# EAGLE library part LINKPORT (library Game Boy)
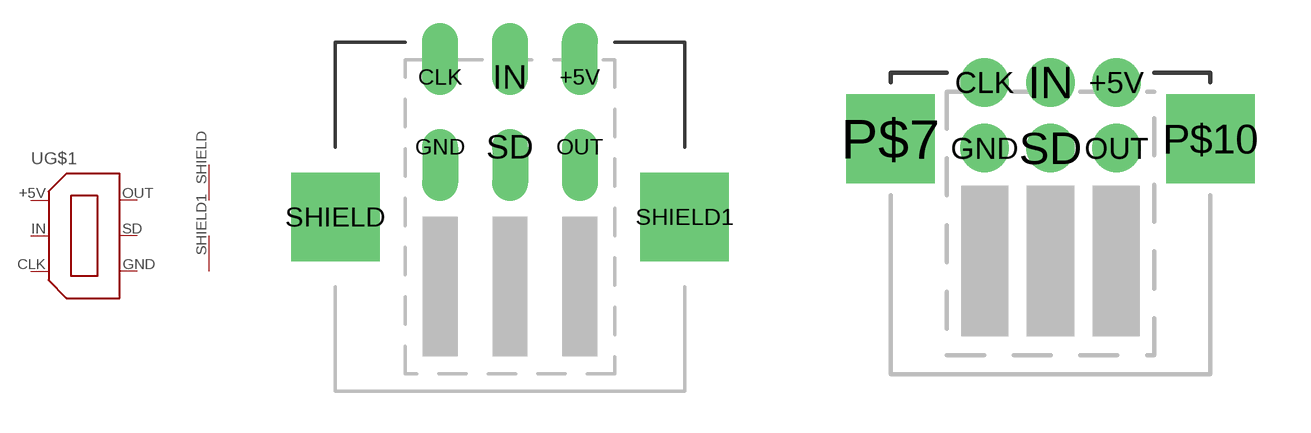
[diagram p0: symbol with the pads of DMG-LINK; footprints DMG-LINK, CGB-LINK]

Designator prefix -; gates G$1=LINK G$2=PWRGND G$3=PWRGND

## LINKPORTDMG-LINK  [DMG-LINK]
+5V  G$1:+5V
CLK  G$1:CLK
GND  G$1:GND
IN  G$1:IN
OUT  G$1:OUT
SD  G$1:SD
SHIELD  G$2:GND  pwr
SHIELD1  G$3:GND  pwr

## LINKPORTCGB-LINK  [CGB-LINK]
+5V  G$1:+5V
CLK  G$1:CLK
GND  G$1:GND
IN  G$1:IN
OUT  G$1:OUT
P$7  G$2:GND  pwr
P$10  G$3:GND  pwr
SD  G$1:SD

## Footprint DMG-LINK (pad centres in mm)
drill 0.8 offset: +5V 2.54,5.08; CLK -2.54,5.08; GND -2.54,2.54; IN 0,5.08; OUT 2.54,2.54; SD 0,2.54
drill 2.2 square: SHIELD -6.35,0; SHIELD1 6.35,0

## Footprint CGB-LINK (pad centres in mm)
drill 0.8 round: +5V 1.778,1.778; CLK -1.778,1.778; GND -1.778,0; IN 0,1.778; OUT 1.778,0; SD 0,0
drill 1.6 pad 2.184 square: P$7 -4.318,0.254; P$10 4.318,0.254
